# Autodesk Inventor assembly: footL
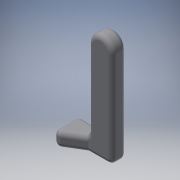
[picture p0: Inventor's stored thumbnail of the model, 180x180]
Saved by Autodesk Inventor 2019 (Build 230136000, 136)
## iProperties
Created: 2020-09
Part Number: footL
Material: 一般
Document SubType Name: Assembly
Designer: kikut
Author: kikut
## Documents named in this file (2)
- F:\openFOAM\basilisk\oversetmeshfootL\footL.iam
- F:\openFOAM\basilisk\oversetmeshfootL\footL.ipt
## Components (1 placed, 1 different names)
1. footL:1 — メイト:1, メイト:2
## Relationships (2: Mate 2)
- メイト:1 [Mate]: footL:1
- メイト:2 [Mate]: footL:1
